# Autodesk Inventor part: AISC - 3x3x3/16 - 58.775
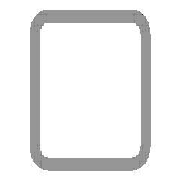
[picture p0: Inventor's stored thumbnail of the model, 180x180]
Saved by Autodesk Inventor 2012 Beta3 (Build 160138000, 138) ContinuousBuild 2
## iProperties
_CCFamilyMember: 9
_CCFamilyDisplayName: ANSI AISC (Square) - Tube
_FrameMemberDoc: Frame Member File
_Version: 15.0.0
_GetPNFromCC: 1
Created: 2011-01
Part Number: AISC - 3x3x3/16 - 58.775
Material: Steel, Mild
Description: Tube
Document SubType Name: Modeling
Standard: ANSI
Designer: Beta-8540w
Standards Organization: ANSI
Language: en-US
Size Designation: 3x3x3/16
Categories: <MemberInstance><Categories><Category DisplayName="Structural Shapes" InternalName="089c4875-fa83-4c05-b084-43b9cc11f5ed" Mnemonic="GRDR"><CategoryParameter Dis
Stock Number: 3x3x3/16
Density: 7.86 g/cm^3
IsCustomPart: 1
G_L: 58.775 in
G_W: 3.000 in
G_H: 3.000 in
+E0C39BE0-1588-4A7D-93DD-AA65CE2CC4A8+CUTDETAIL1: Cut
Author: Beta-8540w
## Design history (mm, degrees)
node "Start plane"
node "End plane"
sketch "Sketch"
  geometry: L1 (-38.1, -28.575)-(-38.1, 28.575); L2 (-28.575, 38.1)-(28.575, 38.1); L3 (38.1, 28.575)-(38.1, -28.575); L4 (28.575, -38.1)-(-28.575, -38.1); L5 (-28.575, 33.337)-(28.575, 33.338); L6 (33.338, 28.575)-(33.338, -28.575); L7 (28.575, -33.337)-(-28.575, -33.338); L8 (-33.338, -28.575)-(-33.338, 28.575); L9 (0, 56.102)-(0, -56.102) reference; L10 (-56.102, 0)-(56.102, 0) reference; A1 r 9.525 centre (-28.575, -28.575) between (-38.1, -28.575) and (-28.575, -38.1); A2 r 9.525 centre (-28.575, 28.575) between (-28.575, 38.1) and (-38.1, 28.575); A3 r 9.525 centre (28.575, 28.575) between (38.1, 28.575) and (28.575, 38.1); A4 r 9.525 centre (28.575, -28.575) between (28.575, -38.1) and (38.1, -28.575); A5 r 4.763 centre (-28.575, 28.575) between (-28.575, 33.337) and (-33.338, 28.575); A6 r 4.763 centre (28.575, 28.575) between (33.338, 28.575) and (28.575, 33.338); A7 r 4.763 centre (28.575, -28.575) between (28.575, -33.337) and (33.338, -28.575); A8 r 4.763 centre (-28.575, -28.575) between (-33.338, -28.575) and (-28.575, -33.338)
  constraints: 16 end point, 16 point on circle, 8 centre point, 8 tangent, 4 parallel, 3 equal radius, 2 perpendicular, 7 other
  dimensions: "d10" = 76.2 distance between parallel lines of L2 L4 (= G_H); "d11" = 76.2 distance between parallel lines of L1 L3 (= G_W); "d12" = 4.7625 distance between parallel lines of L3 L6 (= G_T); "d15" = 38.1 distance between parallel lines of L2 L10 (= 0.5 x d10); "d16" = 38.1 distance between parallel lines of L9 L3 (= 0.5 x d11); "d17" = 9.525 radius of A1 (= G_IR)
extrude "Body" new body sketch "Sketch" stored distance "d3" = 1492.89148 (= G_L); taper "d4" = 0 deg
node "Driven Length"
  sketch "Sketch3"
    geometry: L1 (0, 0)-(10, 0) reference
    constraints: 2 end point, 1 horizontal
  workplane "Work Plane3"
  sketch "Sketch4"
    geometry: L1 (-2, 0)-(12, 0) reference; L2 (-2, 1492.891)-(12, 1492.891) reference
    dimensions: "d19" = 1492.89148 distance between parallel lines of L1 L2 (derived)
workplane "Work Plane4"
split "Split1"
body "Solid1"
other parameters: "G_W" = 76.2 [user parameter; used in 1 equation term], "G_H" = 76.2 [user parameter; used in 1 equation term], "G_T" = 4.7625 [user parameter; used in 1 equation term], "G_IR" = 9.525 [user parameter; used in 1 equation term], "G_L" = 1492.89148 (= d19) [user parameter; used in 1 equation term], "G_OFFSET_START" = 0 [user parameter; used in 1 equation term], "G_OFFSET_END" = -31.10852 [user parameter; used in 1 equation term], "d13" = 0 (computed from G_OFFSET_START), "d14" = 1492.89148 (= G_OFFSET_END + B_L), "B_L" = 1524 [user parameter; used in 1 equation term], "d18" = 90 deg
